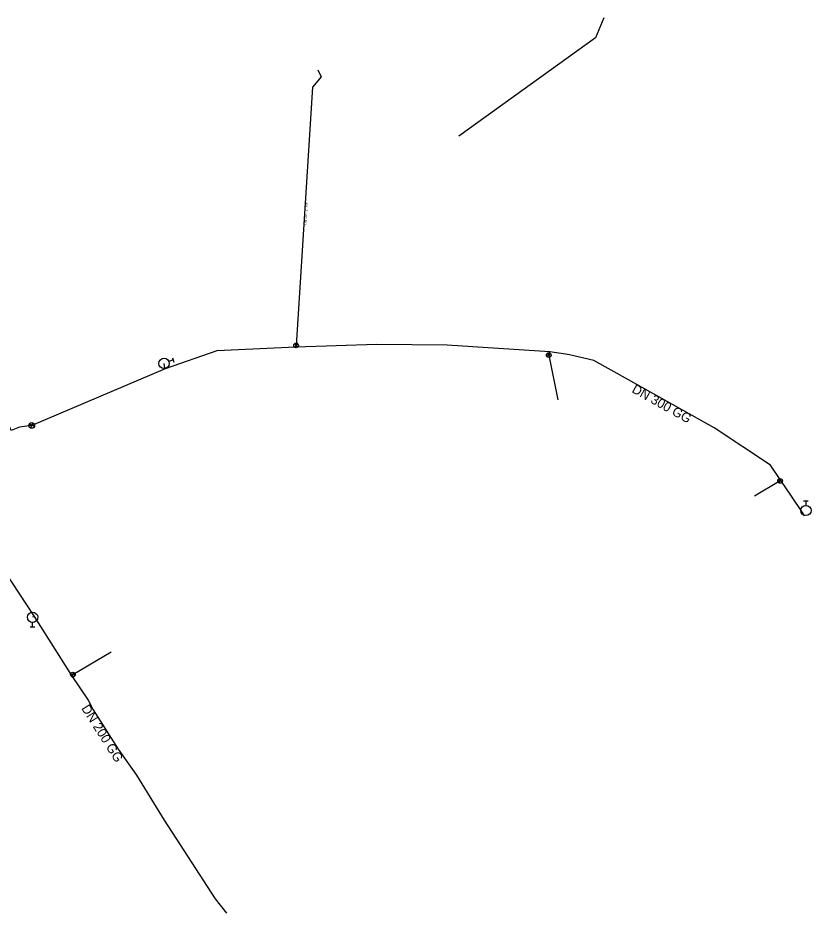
# Model space of a CAD drawing. Extents: x -4927528 to -4924018, y -11264917 to -11262544.
# Drawn here: x -4925380 to -4924018, y -11264093 to -11262555 of the extents above; entities that cross this region are included whole.
import ezdxf

# ---------------------------------------------------------------- set-up
doc = ezdxf.new("R2010")
doc.units = 0
for name, color, linetype in [('_hydrantova_odbocka_', 7, 'Continuous'), ('_pripojka_prevzato_z_dokumentace_', 7, 'Continuous'), ('_pripojka_priblizne_', 7, 'Continuous'), ('_voda_smvak_prevzato_z_dokumentace_', 7, 'Continuous'), ('Default', 7, 'Continuous'), ('MoLevel 27', 7, 'Continuous'), ('MoLevel 28', 7, 'Continuous'), ('MoLevel 32', 7, 'Continuous'), ('MoLevel 46', 7, 'Continuous'), ('MoLevel 53', 7, 'Continuous')]:
    doc.layers.add(name, color=color, linetype=linetype)

# ---------------------------------------------------------------- blocks, each defined once
blk = doc.blocks.new('_uzaver_')
at = {"layer": 'Default'}
for p, q in [((-0.00035, -0.00035), (0.00035, 0.00035)), ((0.00035, -0.00035), (-0.00035, 0.00035))]:
    blk.add_line(p, q, dxfattribs=at)
for radius in [0.0005, 0.000025]:
    blk.add_circle((0, 0), radius, dxfattribs=at)
blk = doc.blocks.new('_uzaver_pripojka_')
at = {"layer": 'Default'}
for p, q in [((-0.00035, -0.00035), (0.00035, 0.00035)), ((0.00035, -0.00035), (-0.00035, 0.00035))]:
    blk.add_line(p, q, dxfattribs=at)
for radius in [0.0005, 0.000025]:
    blk.add_circle((0, 0), radius, dxfattribs=at)
blk = doc.blocks.new('_hydrant_voda_')
at = {"layer": 'Default'}
for p, q in [((-0.000225, 0.00095), (0.000225, 0.00095)), ((0, 0.00095), (0, 0.0005))]:
    blk.add_line(p, q, dxfattribs=at)
blk.add_circle((0, 0), 0.0005, dxfattribs=at)

msp = doc.modelspace()

# ---------------------------------------------------------------- linework, layer by layer
at = {"layer": '_hydrantova_odbocka_'}
msp.add_line((-4925352.4, -11263583.7), (-4925355.2, -11263585), dxfattribs=at)
msp.add_lwpolyline([(-4925127.2, -11263158), (-4925128.4, -11263152.7), (-4925129.4, -11263148.5)], dxfattribs=at)
at = {"layer": '_pripojka_prevzato_z_dokumentace_'}
for points in [[(-4924373.5, -11262554.7), (-4924387.9, -11262588.8), (-4924622.8, -11262757.8)], [(-4925288.4, -11263685), (-4925286, -11263683.4), (-4925220, -11263644.4)]]:
    msp.add_lwpolyline(points, dxfattribs=at)
at = {"layer": '_pripojka_priblizne_'}
for points in [[(-4924865.3, -11262643.8), (-4924859.2, -11262656), (-4924874.4, -11262674), (-4924902.5, -11263117.7), (-4924902.7, -11263120.7)], [(-4924466.5, -11263128.6), (-4924468.5, -11263134.3), (-4924452.9, -11263211.1)], [(-4924069.4, -11263349.7), (-4924071, -11263350.5), (-4924114.7, -11263376.7)]]:
    msp.add_lwpolyline(points, dxfattribs=at)
at = {"layer": '_voda_smvak_prevzato_z_dokumentace_'}
for points in [[(-4925356.8, -11263255.1), (-4925377.7, -11263258.1), (-4925392.2, -11263264.1), (-4925412, -11263219.1), (-4925502, -11263109.5), (-4925524.2, -11263101.8), (-4925562.6, -11263120), (-4925672.3, -11263206)], [(-4924331.5, -11263176.5), (-4924390.8, -11263143.3), (-4924433, -11263133.9), (-4924439.6, -11263132.4), (-4924466.5, -11263128.6), (-4924643, -11263117.3), (-4924764.6, -11263116.2), (-4924902.7, -11263120.7), (-4925038.6, -11263127), (-4925127.2, -11263158), (-4925356.8, -11263255.1)], [(-4924029.1, -11263410.9), (-4924032.3, -11263405.1), (-4924051.5, -11263376.5), (-4924069.4, -11263349.7), (-4924087.7, -11263323.4), (-4924184, -11263259), (-4924331.5, -11263176.5)], [(-4925403.9, -11263505.3), (-4925352.4, -11263583.7), (-4925288.4, -11263685), (-4925260, -11263727.6), (-4925251.4, -11263744), (-4925208.5, -11263811.6), (-4925176.7, -11263856.6), (-4925129.1, -11263933.4), (-4925041.8, -11264068.8), (-4925022.2, -11264093.4)]]:
    msp.add_lwpolyline(points, dxfattribs=at)

# ---------------------------------------------------------------- block references
at = {"layer": 'MoLevel 27', "xscale": 10000, "yscale": 10000, "rotation": 22.404855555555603}
msp.add_blockref('_uzaver_', (-4925356.8, -11263255.1), dxfattribs=at)
at = {"layer": 'MoLevel 28', "xscale": 17636.68430335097}
for p, yscale, rotation in [((-4925129.4, -11263148.5), 17636.684303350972, -69.49222777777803), ((-4925355.2, -11263585), 17636.68430335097, 180)]:
    msp.add_blockref('_hydrant_voda_', p, dxfattribs=dict(at, yscale=yscale, rotation=rotation))
at = {"layer": 'MoLevel 28', "xscale": 17636.68430335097, "yscale": 17636.68430335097}
msp.add_blockref('_hydrant_voda_', (-4924026.5, -11263401.4), dxfattribs=at)
at = {"layer": 'MoLevel 53'}
for p, xscale, yscale, rotation in [((-4924902.5, -11263117.7), 7999.999999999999, 7999.999999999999, -89.87928333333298), ((-4924468.5, -11263134.3), 7999.999999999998, 7999.999999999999, 80.9567027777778), ((-4924071, -11263350.5), 7999.999999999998, 8000.000000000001, 14.901475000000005), ((-4925286, -11263683.4), 8000, 8000, -59.44165555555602)]:
    msp.add_blockref('_uzaver_pripojka_', p, dxfattribs=dict(at, xscale=xscale, yscale=yscale, rotation=rotation))

# ---------------------------------------------------------------- texts
at = {"layer": 'MoLevel 32'}
msp.add_text("DN 50 - 2'' PE", height=4.55, rotation=86.3786, dxfattribs=at).set_placement((-4924884.8, -11262910.6))
at = {"layer": 'MoLevel 46'}
for s, rotation, p in [('DN 300 GG', 330.7827, (-4924327, -11263197.4)), ('DN 200 GG', 302.3998, (-4925272.1, -11263741.4))]:
    msp.add_text(s, height=16.05, rotation=rotation, dxfattribs=at).set_placement(p)

doc.saveas('drawing.dxf')
